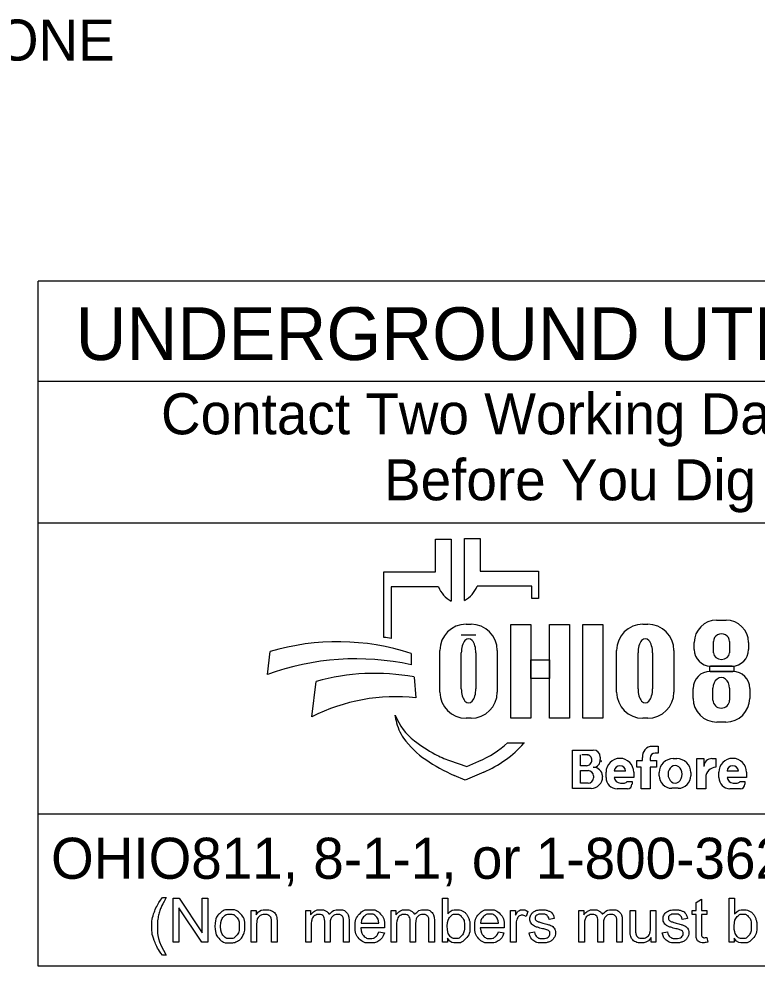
# Model space of a CAD drawing. Extents: x 0 to 34, y 0 to 22.
# Drawn here: x 2.312 to 4.831, y 2.143 to 5.374 of the extents above; entities that cross this region are included whole.
import ezdxf

# ---------------------------------------------------------------- set-up
doc = ezdxf.new("R2010")
doc.units = 0
doc.layers.add('SH_Data', color=7, linetype='Continuous')
doc.layers.add('SH_Text', color=7, linetype='Continuous')

msp = doc.modelspace()

# ---------------------------------------------------------------- linework, layer by layer
at = {"layer": 'SH_Data'}
for p, q in [((2.3775, 2.1428), (2.3775, 4.4803)), ((6.6275, 4.4803), (2.3775, 4.4803)), ((2.3775, 4.1387), (6.6275, 4.1387)), ((2.3775, 3.6553), (6.6275, 3.6553)), ((6.6275, 2.6607), (2.3775, 2.6607)), ((6.6275, 2.1428), (2.3775, 2.1428))]:
    msp.add_line(p, q, dxfattribs=at)
at = {"layer": 'SH_Text'}
for p, q in [((3.7335, 3.4883), (3.7335, 3.5998)), ((3.7335, 3.5998), (3.7872, 3.5998)), ((3.7872, 3.5998), (3.7872, 3.3877)), ((3.8329, 3.39), (3.8329, 3.6021)), ((3.8329, 3.6021), (3.8865, 3.6021)), ((3.8865, 3.6021), (3.8865, 3.4906)), ((3.8865, 3.4906), (4.0857, 3.4906)), ((4.0857, 3.4906), (4.0857, 3.3968)), ((3.5576, 3.2644), (3.5576, 3.4883)), ((3.5576, 3.4883), (3.7335, 3.4883)), ((3.5828, 3.4369), (3.5828, 3.26)), ((3.7439, 3.4369), (3.5828, 3.4369)), ((4.0625, 3.4392), (3.8761, 3.4392)), ((4.0625, 3.3968), (4.0625, 3.4392)), ((4.0857, 3.3968), (4.0625, 3.3968)), ((3.8385, 3.3091), (3.8551, 3.3091)), ((4.4416, 3.3091), (4.4581, 3.3091)), ((4.6931, 3.3231), (4.7258, 3.3231)), ((3.8718, 3.2721), (3.822, 3.2721)), ((4.6168, 3.2225), (4.6168, 3.2468)), ((4.683, 3.2111), (4.683, 3.2504)), ((4.7371, 3.2504), (4.7371, 3.2111)), ((4.8022, 3.2468), (4.8022, 3.2225)), ((3.1602, 3.1381), (3.1696, 3.2162)), ((3.6509, 3.2097), (3.6509, 3.1709)), ((3.7491, 3.0776), (3.7491, 3.2196)), ((3.822, 3.089), (3.822, 3.2114)), ((3.8718, 3.2114), (3.8718, 3.089)), ((3.9445, 3.2196), (3.9445, 3.0776)), ((4.3521, 3.0776), (4.3521, 3.2196)), ((4.425, 3.089), (4.425, 3.2114)), ((4.4748, 3.2114), (4.4748, 3.089)), ((4.5476, 3.2196), (4.5476, 3.0776)), ((4.671, 3.1482), (4.7483, 3.1482)), ((4.7462, 3.1665), (4.6728, 3.1665)), ((3.312, 2.9936), (3.3267, 3.1137)), ((3.6608, 3.1291), (3.6671, 3.0582)), ((4.6131, 3.0563), (4.6131, 3.0903)), ((4.6806, 3.0503), (4.6806, 3.0912)), ((4.7374, 3.0912), (4.7374, 3.0503)), ((4.8062, 3.0903), (4.8062, 3.0563)), ((3.5997, 2.9807), (3.5967, 2.9986)), ((3.8551, 2.9882), (3.8385, 2.9882)), ((4.4581, 2.9882), (4.4416, 2.9882)), ((4.7252, 2.9753), (4.6941, 2.9753)), ((3.98, 2.9048), (4.0375, 2.9048)), ((4.2013, 2.749), (4.2013, 2.8798)), ((4.2013, 2.8798), (4.2725, 2.8798)), ((4.4739, 2.8926), (4.4934, 2.8926)), ((4.4934, 2.8926), (4.4934, 2.8696)), ((3.7816, 2.8444), (3.841, 2.8239)), ((4.2293, 2.8263), (4.2293, 2.8632)), ((4.2545, 2.8632), (4.2332, 2.8632)), ((4.2963, 2.856), (4.2963, 2.8481)), ((4.4213, 2.8212), (4.4213, 2.8442)), ((4.4213, 2.8442), (4.4406, 2.8442)), ((4.4406, 2.8442), (4.4406, 2.8546)), ((4.4667, 2.8526), (4.4667, 2.8442)), ((4.4667, 2.8442), (4.4883, 2.8442)), ((4.4934, 2.8691), (4.4832, 2.8691)), ((4.4883, 2.8442), (4.4883, 2.8212)), ((4.5451, 2.8508), (4.5573, 2.8508)), ((4.6254, 2.7478), (4.6254, 2.8505)), ((4.6254, 2.8505), (4.6499, 2.8505)), ((4.6499, 2.8505), (4.6499, 2.8237)), ((4.6772, 2.8505), (4.691, 2.8505)), ((4.691, 2.8505), (4.691, 2.8209)), ((3.841, 2.8239), (3.8821, 2.8417)), ((4.2487, 2.8263), (4.2293, 2.8263)), ((4.4362, 2.8212), (4.4213, 2.8212)), ((4.4362, 2.7478), (4.4362, 2.8212)), ((4.4883, 2.8212), (4.4667, 2.8212)), ((4.4667, 2.8212), (4.4667, 2.7478)), ((3.835, 2.7769), (3.7976, 2.7934)), ((3.8983, 2.8044), (3.835, 2.7769)), ((4.2293, 2.7669), (4.2293, 2.8097)), ((4.2293, 2.8097), (4.2548, 2.8097)), ((4.2729, 2.7916), (4.2729, 2.7853)), ((4.3043, 2.7887), (4.3043, 2.7884)), ((4.3159, 2.7858), (4.3159, 2.8042)), ((4.3824, 2.8082), (4.3439, 2.8082)), ((4.4104, 2.7866), (4.344, 2.7866)), ((4.4104, 2.8042), (4.4104, 2.7866)), ((4.4973, 2.7922), (4.4973, 2.8029)), ((4.6051, 2.8029), (4.6051, 2.7922)), ((4.6559, 2.786), (4.6559, 2.7478)), ((4.7008, 2.7858), (4.7008, 2.8042)), ((4.7674, 2.8082), (4.7288, 2.8082)), ((4.7953, 2.7866), (4.7289, 2.7866)), ((4.7953, 2.8042), (4.7953, 2.7866)), ((4.265, 2.749), (4.2013, 2.749)), ((4.2546, 2.7669), (4.2293, 2.7669)), ((4.3892, 2.7478), (4.3538, 2.7478)), ((4.3649, 2.7673), (4.379, 2.7673)), ((4.3876, 2.7729), (4.4045, 2.7729)), ((4.4045, 2.7729), (4.4045, 2.7631)), ((4.4667, 2.7478), (4.4362, 2.7478)), ((4.5623, 2.7494), (4.5401, 2.7494)), ((4.6559, 2.7478), (4.6254, 2.7478)), ((4.7742, 2.7478), (4.7388, 2.7478)), ((4.7498, 2.7673), (4.7639, 2.7673)), ((4.7725, 2.7729), (4.7894, 2.7729)), ((4.7894, 2.7729), (4.7894, 2.7631))]:
    msp.add_line(p, q, dxfattribs=at)
for points in [[(3.991, 3.3081), (4.0589, 3.3081), (4.0589, 2.9881), (3.991, 2.9881)], [(4.1231, 3.3081), (4.1911, 3.3081), (4.1911, 2.9881), (4.1231, 2.9881)], [(4.2364, 3.3081), (4.3052, 3.3081), (4.3052, 2.9881), (4.2364, 2.9881)], [(4.0589, 3.1882), (4.1231, 3.1882), (4.1231, 3.1242), (4.0589, 3.1242)], [(4.6706, 3.1665), (4.7523, 3.1665), (4.7523, 3.1481), (4.6706, 3.1481)]]:
    msp.add_lwpolyline(points, close=True, dxfattribs=at)
for points in [[(2.8021, 2.3766), (2.8153, 2.3766)], [(2.8389, 2.2239), (2.8389, 2.3741), (2.8592, 2.3741), (2.9382, 2.2561), (2.9382, 2.3741), (2.9572, 2.3741), (2.9572, 2.2239), (2.9369, 2.2239), (2.8579, 2.3419), (2.8579, 2.2239), (2.8389, 2.2239)], [(3.7743, 2.2239), (3.7573, 2.2239), (3.7573, 2.3741), (3.7757, 2.3741), (3.7757, 2.3206)], [(4.6233, 2.2558), (4.6233, 2.3185), (4.6097, 2.3185), (4.6097, 2.3328), (4.6233, 2.3328), (4.6233, 2.3597), (4.6417, 2.3708), (4.6417, 2.3328), (4.6601, 2.3328), (4.6601, 2.3185), (4.6417, 2.3185), (4.6417, 2.2547)], [(4.7534, 2.2239), (4.7363, 2.2239), (4.7363, 2.3741), (4.7548, 2.3741), (4.7548, 2.3206)], [(3.1048, 2.2239), (3.1048, 2.3328), (3.1214, 2.3328), (3.1214, 2.3173)], [(3.2912, 2.2239), (3.2912, 2.3328), (3.3077, 2.3328), (3.3077, 2.3174)], [(3.5826, 2.2239), (3.5826, 2.3328), (3.5991, 2.3328), (3.5991, 2.3174)], [(3.9904, 2.2239), (3.9904, 2.3328), (4.007, 2.3328), (4.007, 2.3163)], [(4.0495, 2.3293), (4.043, 2.3122)], [(4.2236, 2.2239), (4.2236, 2.3328), (4.2401, 2.3328), (4.2401, 2.3174)], [(4.3979, 2.2654), (4.3979, 2.3328), (4.4164, 2.3328), (4.4164, 2.2724)], [(4.4676, 2.2745), (4.4676, 2.3328), (4.4861, 2.3328), (4.4861, 2.2239), (4.4696, 2.2239)], [(3.3743, 2.2871), (3.3743, 2.2239), (3.3559, 2.2239), (3.3559, 2.2946)], [(3.4388, 2.2986), (3.4388, 2.2239), (3.4203, 2.2239), (3.4203, 2.2924)], [(3.6657, 2.2871), (3.6657, 2.2239), (3.6473, 2.2239), (3.6473, 2.2946)], [(3.7301, 2.2986), (3.7301, 2.2239), (3.7117, 2.2239), (3.7117, 2.2924)], [(4.1394, 2.3046), (4.1213, 2.3022)], [(4.3067, 2.2871), (4.3067, 2.2239), (4.2883, 2.2239), (4.2883, 2.2946)], [(4.3711, 2.2986), (4.3711, 2.2239), (4.3527, 2.2239), (4.3527, 2.2924)], [(4.594, 2.3046), (4.5759, 2.3022)], [(3.1233, 2.2833), (3.1233, 2.2239), (3.1048, 2.2239)], [(3.1932, 2.2908), (3.1932, 2.2239), (3.1748, 2.2239), (3.1748, 2.2901)], [(3.3097, 2.2803), (3.3097, 2.2239), (3.2912, 2.2239)], [(3.56, 2.2736), (3.4788, 2.2736)], [(3.4799, 2.2887), (3.5406, 2.2887)], [(3.601, 2.2803), (3.601, 2.2239), (3.5826, 2.2239)], [(3.968, 2.2736), (3.8868, 2.2736)], [(3.8879, 2.2887), (3.9486, 2.2887)], [(4.0088, 2.2809), (4.0088, 2.2239), (3.9904, 2.2239)], [(4.242, 2.2803), (4.242, 2.2239), (4.2236, 2.2239)], [(3.5404, 2.2591), (3.5595, 2.2567)], [(3.7743, 2.2375), (3.7743, 2.2239)], [(3.9484, 2.2591), (3.9675, 2.2567)], [(4.053, 2.2564), (4.0712, 2.2593)], [(4.4696, 2.2239), (4.4696, 2.24)], [(4.5076, 2.2564), (4.5258, 2.2593)], [(4.6601, 2.2404), (4.6628, 2.2241)], [(4.7534, 2.2375), (4.7534, 2.2239)], [(2.8153, 2.1798), (2.8021, 2.1798)]]:
    msp.add_lwpolyline(points, dxfattribs=at)
for centre, radius, start, end in [((3.8353, 3.4736), 0.0985, 201.9296, 240.7469), ((3.7847, 3.476), 0.0985, 299.2531, 338.0704), ((3.8385, 3.2196), 0.0895, 90, 180), ((3.8551, 3.2196), 0.0895, 0, 90), ((4.4416, 3.2196), 0.0895, 90, 180), ((4.4581, 3.2196), 0.0895, 0, 90), ((4.6931, 3.2468), 0.0763, 90, 180), ((4.7258, 3.2468), 0.0763, 0, 90), ((3.4295, 2.4554), 0.8191, 79.2074, 81.0007), ((3.3997, 2.4302), 0.8191, 72.1402, 106.3144), ((4.6728, 3.2225), 0.056, 180, 270), ((4.7462, 3.2225), 0.056, 270, 0), ((3.4628, 2.2991), 0.8919, 77.8238, 109.8274), ((3.5267, 2.4094), 0.7322, 79.44, 105.8467), ((4.671, 3.0903), 0.0579, 90, 180), ((4.7483, 3.0903), 0.0579, 0, 90), ((3.8385, 3.0776), 0.0895, 180, 270), ((3.8551, 3.0776), 0.0895, 270, 0), ((4.4416, 3.0776), 0.0895, 180, 270), ((4.4581, 3.0776), 0.0895, 270, 0), ((3.5987, 2.4262), 0.6357, 83.8248, 116.8021), ((4.6941, 3.0563), 0.081, 180, 270), ((4.7252, 3.0563), 0.081, 270, 0), ((3.7841, 3.0707), 0.2008, 201.0457, 232.5314), ((3.741, 3.0048), 0.1433, 189.6817, 216.0884), ((3.8747, 3.1022), 0.3088, 216.0884, 235.7167), ((3.9766, 3.3219), 0.5173, 232.5314, 241.794), ((3.7387, 3.1722), 0.3602, 293.4582, 312.0712), ((3.7387, 3.1722), 0.401, 293.4582, 317.8286), ((4.2725, 2.856), 0.0238, 0, 90), ((4.4739, 2.859), 0.0335, 90, 187.5187), ((4.0412, 3.3465), 0.6044, 235.7167, 246.2325), ((3.8914, 3.1631), 0.3371, 241.794, 250.9821), ((4.2487, 2.845), 0.0187, 270, 2.0582), ((4.2505, 2.8463), 0.0169, 357.8325, 90), ((4.2721, 2.8453), 0.0243, 270, 6.6529), ((4.3631, 2.8042), 0.0473, 0, 180), ((4.4832, 2.8526), 0.0165, 90, 180), ((4.5451, 2.8029), 0.0478, 90, 180), ((4.5573, 2.8029), 0.0478, 0, 90), ((4.6768, 2.8237), 0.0269, 89.2449, 180), ((4.7481, 2.8042), 0.0473, 0, 180), ((4.2722, 2.7889), 0.0321, 4.0748, 90), ((4.2827, 2.8438), 0.0175, 347.4023, 0), ((4.3632, 2.8072), 0.0193, 2.9632, 177.0368), ((4.6908, 2.786), 0.0349, 89.6033, 180), ((4.7481, 2.8072), 0.0193, 2.9632, 177.0368), ((4.2546, 2.7853), 0.0184, 270, 0), ((4.2548, 2.7916), 0.0181, 0, 90), ((4.265, 2.7884), 0.0393, 270, 0), ((4.2714, 2.7887), 0.033, 0, 11.7502), ((4.3538, 2.7858), 0.038, 180, 270), ((4.3649, 2.7883), 0.021, 184.827, 270), ((4.5401, 2.7922), 0.0428, 180, 270), ((4.5623, 2.7922), 0.0428, 270, 0), ((4.7388, 2.7858), 0.038, 180, 270), ((4.7498, 2.7883), 0.021, 184.827, 270), ((4.379, 2.7767), 0.00938, 270, 335.9979), ((4.3892, 2.7631), 0.0152, 270, 0), ((4.7639, 2.7767), 0.00938, 270, 335.9979), ((4.7742, 2.7631), 0.0152, 270, 0)]:
    msp.add_arc(centre, radius, start, end, dxfattribs=at)
for centre, major_axis, ratio, start_param, end_param in [((4.71, 3.2504), (0.0271, 0), 0.969373, 0, 3.141593), ((3.8469, 3.2114), (0, 0.0484), 0.514403, 4.712389, 7.853982), ((4.4499, 3.2114), (0, 0.0484), 0.514403, 4.712389, 7.853982), ((4.71, 3.2111), (0.0271, 0), 0.818453, 3.141593, 6.283185), ((4.709, 3.0912), (0, 0.0358), 0.794529, 4.712389, 7.853982), ((3.8469, 3.089), (0, 0.0484), 0.514403, 1.570796, 4.712389), ((4.4499, 3.089), (0, 0.0484), 0.514403, 1.570796, 4.712389), ((4.709, 3.0503), (0.0284, 0), 0.959837, 3.141593, 6.283185), ((4.5517, 2.7976), (0, 0.029), 0.832186, 4.712389, 7.853982), ((4.5517, 2.7976), (0, 0.0302), 0.797287, 1.570796, 4.712389)]:
    msp.add_ellipse(centre, major_axis=major_axis, ratio=ratio, start_param=start_param, end_param=end_param, dxfattribs=at)
for points in [[(2.8021, 2.1798), (2.7869, 2.199), (2.7763, 2.2248), (2.7657, 2.2506), (2.7657, 2.2783), (2.7657, 2.3026), (2.7736, 2.325), (2.7829, 2.3509), (2.8021, 2.3766)], [(2.8153, 2.3766), (2.8029, 2.3553), (2.7989, 2.3462), (2.7927, 2.332), (2.7891, 2.3167), (2.7847, 2.2975), (2.7847, 2.2782), (2.7847, 2.2289), (2.8153, 2.1798)], [(2.9814, 2.2783), (2.9814, 2.3085), (2.9981, 2.3231), (3.0122, 2.3352), (3.0323, 2.3352), (3.0547, 2.3352), (3.069, 2.3205), (3.0832, 2.3058), (3.0832, 2.2799), (3.0832, 2.2589), (3.0769, 2.2469), (3.0706, 2.2348), (3.0586, 2.2282), (3.0466, 2.2215), (3.0323, 2.2215), (3.0095, 2.2215), (2.9954, 2.2362), (2.9814, 2.2508), (2.9814, 2.2783)], [(3.1214, 2.3173), (3.1334, 2.3352), (3.156, 2.3352), (3.1659, 2.3352), (3.1741, 2.3316), (3.1823, 2.3281), (3.1864, 2.3224), (3.1905, 2.3166), (3.1922, 2.3087), (3.1932, 2.3036), (3.1932, 2.2908)], [(3.3077, 2.3174), (3.3128, 2.3254), (3.3214, 2.3303), (3.3299, 2.3352), (3.3407, 2.3352), (3.3528, 2.3352), (3.3606, 2.3301), (3.3683, 2.3251), (3.3715, 2.3161), (3.3844, 2.3352), (3.4051, 2.3352), (3.4213, 2.3352), (3.43, 2.3262), (3.4388, 2.3172), (3.4388, 2.2986)], [(3.5595, 2.2567), (3.555, 2.24), (3.5428, 2.2307), (3.5306, 2.2215), (3.5117, 2.2215), (3.4878, 2.2215), (3.4738, 2.2362), (3.4598, 2.2509), (3.4598, 2.2774), (3.4598, 2.3049), (3.474, 2.32), (3.4881, 2.3352), (3.5106, 2.3352), (3.5324, 2.3352), (3.5463, 2.3203), (3.5601, 2.3055), (3.5601, 2.2785), (3.5601, 2.2769), (3.56, 2.2736)], [(3.5991, 2.3174), (3.6042, 2.3254), (3.6127, 2.3303), (3.6212, 2.3352), (3.6321, 2.3352), (3.6442, 2.3352), (3.6519, 2.3301), (3.6597, 2.3251), (3.6628, 2.3161), (3.6758, 2.3352), (3.6965, 2.3352), (3.7127, 2.3352), (3.7214, 2.3262), (3.7301, 2.3172), (3.7301, 2.2986)], [(3.7757, 2.3206), (3.7874, 2.3352), (3.8055, 2.3352), (3.8155, 2.3352), (3.8245, 2.3311), (3.8335, 2.3271), (3.8392, 2.3198), (3.845, 2.3124), (3.8483, 2.3021), (3.8516, 2.2918), (3.8516, 2.28), (3.8516, 2.252), (3.8378, 2.2368), (3.8239, 2.2215), (3.8046, 2.2215), (3.7853, 2.2215), (3.7743, 2.2375)], [(3.9675, 2.2567), (3.963, 2.24), (3.9508, 2.2307), (3.9386, 2.2215), (3.9196, 2.2215), (3.8958, 2.2215), (3.8818, 2.2362), (3.8678, 2.2509), (3.8678, 2.2774), (3.8678, 2.3049), (3.882, 2.32), (3.8961, 2.3352), (3.9186, 2.3352), (3.9404, 2.3352), (3.9543, 2.3203), (3.9681, 2.3055), (3.9681, 2.2785), (3.9681, 2.2769), (3.968, 2.2736)], [(4.007, 2.3163), (4.0133, 2.3278), (4.0187, 2.3315), (4.0241, 2.3352), (4.0305, 2.3352), (4.0398, 2.3352), (4.0495, 2.3293)], [(4.0712, 2.2593), (4.0727, 2.2483), (4.0798, 2.2425), (4.0868, 2.2366), (4.0995, 2.2366), (4.1122, 2.2366), (4.1184, 2.2418), (4.1245, 2.247), (4.1245, 2.254), (4.1245, 2.2602), (4.1191, 2.2638), (4.1153, 2.2663), (4.1002, 2.2701), (4.0799, 2.2752), (4.072, 2.2789), (4.0642, 2.2827), (4.0601, 2.2893), (4.0561, 2.2959), (4.0561, 2.3038), (4.0561, 2.3111), (4.0594, 2.3173), (4.0628, 2.3235), (4.0685, 2.3276), (4.0728, 2.3308), (4.0803, 2.333), (4.0877, 2.3352), (4.0962, 2.3352), (4.109, 2.3352), (4.1187, 2.3315), (4.1284, 2.3278), (4.133, 2.3215), (4.1377, 2.3152), (4.1394, 2.3046)], [(4.2401, 2.3174), (4.2452, 2.3254), (4.2537, 2.3303), (4.2622, 2.3352), (4.2731, 2.3352), (4.2852, 2.3352), (4.2929, 2.3301), (4.3007, 2.3251), (4.3038, 2.3161), (4.3168, 2.3352), (4.3375, 2.3352), (4.3537, 2.3352), (4.3624, 2.3262), (4.3711, 2.3172), (4.3711, 2.2986)], [(4.5258, 2.2593), (4.5273, 2.2483), (4.5343, 2.2425), (4.5414, 2.2366), (4.554, 2.2366), (4.5668, 2.2366), (4.5729, 2.2418), (4.5791, 2.247), (4.5791, 2.254), (4.5791, 2.2602), (4.5736, 2.2638), (4.5698, 2.2663), (4.5548, 2.2701), (4.5345, 2.2752), (4.5266, 2.2789), (4.5188, 2.2827), (4.5147, 2.2893), (4.5107, 2.2959), (4.5107, 2.3038), (4.5107, 2.3111), (4.514, 2.3173), (4.5173, 2.3235), (4.5231, 2.3276), (4.5274, 2.3308), (4.5348, 2.333), (4.5423, 2.3352), (4.5508, 2.3352), (4.5636, 2.3352), (4.5733, 2.3315), (4.583, 2.3278), (4.5876, 2.3215), (4.5922, 2.3152), (4.594, 2.3046)], [(4.7548, 2.3206), (4.7664, 2.3352), (4.7846, 2.3352), (4.7946, 2.3352), (4.8036, 2.3311), (4.8125, 2.3271), (4.8183, 2.3198), (4.8241, 2.3124), (4.8274, 2.3021), (4.8306, 2.2918), (4.8306, 2.28), (4.8306, 2.252), (4.8168, 2.2368), (4.803, 2.2215), (4.7836, 2.2215), (4.7644, 2.2215), (4.7534, 2.2375)], [(3.0003, 2.2783), (3.0003, 2.2574), (3.0094, 2.247), (3.0185, 2.2366), (3.0323, 2.2366), (3.046, 2.2366), (3.0551, 2.2471), (3.0642, 2.2575), (3.0642, 2.279), (3.0642, 2.2991), (3.0551, 2.3095), (3.0459, 2.3199), (3.0323, 2.3199), (3.0185, 2.3199), (3.0094, 2.3096), (3.0003, 2.2992), (3.0003, 2.2783)], [(3.1748, 2.2901), (3.1748, 2.3013), (3.1726, 2.3069), (3.1705, 2.3125), (3.165, 2.3158), (3.1595, 2.3191), (3.1521, 2.3191), (3.1404, 2.3191), (3.1318, 2.3117), (3.1233, 2.3042), (3.1233, 2.2833)], [(3.3559, 2.2946), (3.3559, 2.3069), (3.3514, 2.313), (3.3469, 2.3191), (3.3366, 2.3191), (3.3288, 2.3191), (3.3222, 2.315), (3.3156, 2.311), (3.3126, 2.3031), (3.3097, 2.2952), (3.3097, 2.2803)], [(3.4203, 2.2924), (3.4203, 2.3035), (3.4185, 2.3083), (3.4168, 2.3132), (3.412, 2.3162), (3.4073, 2.3191), (3.401, 2.3191), (3.3895, 2.3191), (3.3819, 2.3115), (3.3743, 2.3039), (3.3743, 2.2871)], [(3.5406, 2.2887), (3.5394, 2.3025), (3.5337, 2.3094), (3.5249, 2.3201), (3.5108, 2.3201), (3.4981, 2.3201), (3.4894, 2.3115), (3.4808, 2.303), (3.4799, 2.2887)], [(3.6473, 2.2946), (3.6473, 2.3069), (3.6428, 2.313), (3.6383, 2.3191), (3.628, 2.3191), (3.6202, 2.3191), (3.6136, 2.315), (3.607, 2.311), (3.604, 2.3031), (3.601, 2.2952), (3.601, 2.2803)], [(3.7117, 2.2924), (3.7117, 2.3035), (3.7099, 2.3083), (3.7081, 2.3132), (3.7034, 2.3162), (3.6987, 2.3191), (3.6923, 2.3191), (3.6809, 2.3191), (3.6733, 2.3115), (3.6657, 2.3039), (3.6657, 2.2871)], [(3.7741, 2.2792), (3.7741, 2.2596), (3.7794, 2.2509), (3.7881, 2.2366), (3.8029, 2.2366), (3.815, 2.2366), (3.8238, 2.2471), (3.8326, 2.2576), (3.8326, 2.2784), (3.8326, 2.2998), (3.8241, 2.3099), (3.8157, 2.3201), (3.8038, 2.3201), (3.7917, 2.3201), (3.7829, 2.3096), (3.7741, 2.299), (3.7741, 2.2792)], [(3.9486, 2.2887), (3.9474, 2.3025), (3.9417, 2.3094), (3.9328, 2.3201), (3.9188, 2.3201), (3.9061, 2.3201), (3.8974, 2.3115), (3.8888, 2.303), (3.8879, 2.2887)], [(4.043, 2.3122), (4.0363, 2.3162), (4.0295, 2.3162), (4.0235, 2.3162), (4.0187, 2.3125), (4.0139, 2.3089), (4.0119, 2.3024), (4.0088, 2.2926), (4.0088, 2.2809)], [(4.1213, 2.3022), (4.1201, 2.3106), (4.1142, 2.3153), (4.1083, 2.3201), (4.0975, 2.3201), (4.0848, 2.3201), (4.0794, 2.3159), (4.0739, 2.3116), (4.0739, 2.306), (4.0739, 2.3024), (4.0762, 2.2995), (4.0785, 2.2966), (4.0833, 2.2946), (4.086, 2.2936), (4.0996, 2.2899), (4.1192, 2.2847), (4.1269, 2.2813), (4.1347, 2.278), (4.1391, 2.2717), (4.1435, 2.2653), (4.1435, 2.2559), (4.1435, 2.2467), (4.1381, 2.2386), (4.1327, 2.2304), (4.1226, 2.226), (4.1124, 2.2215), (4.0996, 2.2215), (4.0784, 2.2215), (4.0672, 2.2303), (4.0561, 2.2391), (4.053, 2.2564)], [(4.2883, 2.2946), (4.2883, 2.3069), (4.2838, 2.313), (4.2793, 2.3191), (4.269, 2.3191), (4.2612, 2.3191), (4.2546, 2.315), (4.248, 2.311), (4.245, 2.3031), (4.242, 2.2952), (4.242, 2.2803)], [(4.3527, 2.2924), (4.3527, 2.3035), (4.3509, 2.3083), (4.3491, 2.3132), (4.3444, 2.3162), (4.3397, 2.3191), (4.3333, 2.3191), (4.3219, 2.3191), (4.3143, 2.3115), (4.3067, 2.3039), (4.3067, 2.2871)], [(4.5759, 2.3022), (4.5747, 2.3106), (4.5688, 2.3153), (4.5629, 2.3201), (4.5521, 2.3201), (4.5394, 2.3201), (4.5339, 2.3159), (4.5285, 2.3116), (4.5285, 2.306), (4.5285, 2.3024), (4.5308, 2.2995), (4.533, 2.2966), (4.5378, 2.2946), (4.5406, 2.2936), (4.5542, 2.2899), (4.5737, 2.2847), (4.5815, 2.2813), (4.5893, 2.278), (4.5937, 2.2717), (4.5981, 2.2653), (4.5981, 2.2559), (4.5981, 2.2467), (4.5927, 2.2386), (4.5873, 2.2304), (4.5772, 2.226), (4.567, 2.2215), (4.5542, 2.2215), (4.5329, 2.2215), (4.5218, 2.2303), (4.5107, 2.2391), (4.5076, 2.2564)], [(4.7532, 2.2792), (4.7532, 2.2596), (4.7585, 2.2509), (4.7672, 2.2366), (4.782, 2.2366), (4.7941, 2.2366), (4.8029, 2.2471), (4.8116, 2.2576), (4.8116, 2.2784), (4.8116, 2.2998), (4.8032, 2.3099), (4.7948, 2.3201), (4.7828, 2.3201), (4.7708, 2.3201), (4.762, 2.3096), (4.7532, 2.299), (4.7532, 2.2792)], [(3.4788, 2.2736), (3.4799, 2.2557), (3.489, 2.2462), (3.4981, 2.2366), (3.5117, 2.2366), (3.5219, 2.2366), (3.5291, 2.242), (3.5362, 2.2473), (3.5404, 2.2591)], [(3.8868, 2.2736), (3.8879, 2.2557), (3.897, 2.2462), (3.9061, 2.2366), (3.9197, 2.2366), (3.9299, 2.2366), (3.937, 2.242), (3.9442, 2.2473), (3.9484, 2.2591)], [(4.4696, 2.24), (4.4569, 2.2215), (4.4351, 2.2215), (4.4255, 2.2215), (4.4171, 2.2252), (4.4088, 2.2289), (4.4047, 2.2345), (4.4007, 2.2401), (4.3991, 2.2482), (4.3979, 2.2536), (4.3979, 2.2654)], [(4.4164, 2.2724), (4.4164, 2.258), (4.4175, 2.253), (4.4192, 2.2457), (4.4249, 2.2416), (4.4305, 2.2374), (4.4388, 2.2374), (4.4471, 2.2374), (4.4543, 2.2417), (4.4616, 2.2459), (4.4646, 2.2533), (4.4676, 2.2606), (4.4676, 2.2745)], [(4.6628, 2.2241), (4.655, 2.2224), (4.6488, 2.2224), (4.6388, 2.2224), (4.6333, 2.2256), (4.6278, 2.2288), (4.6255, 2.234), (4.6233, 2.2392), (4.6233, 2.2558)], [(4.6417, 2.2547), (4.6417, 2.2468), (4.6427, 2.2445), (4.6436, 2.2423), (4.6458, 2.2409), (4.648, 2.2396), (4.6521, 2.2396), (4.6551, 2.2396), (4.6601, 2.2404)]]:
    msp.add_open_spline(points, degree=3, dxfattribs=at)

# ---------------------------------------------------------------- texts
for s, height, p in [('  NONE                                   ', 0.14, (1.9944, 5.2324)), ('UNDERGROUND UTILITIES', 0.18, (2.5057, 4.2106)), ('Contact Two Working Days', 0.14, (2.7972, 3.9571)), ('Before You Dig', 0.14, (3.5583, 3.7321)), ('OHIO811, 8-1-1, or 1-800-362-2764', 0.14, (2.422, 2.4406))]:
    msp.add_text(s, height=height, dxfattribs=at).set_placement(p)

doc.saveas('drawing.dxf')
